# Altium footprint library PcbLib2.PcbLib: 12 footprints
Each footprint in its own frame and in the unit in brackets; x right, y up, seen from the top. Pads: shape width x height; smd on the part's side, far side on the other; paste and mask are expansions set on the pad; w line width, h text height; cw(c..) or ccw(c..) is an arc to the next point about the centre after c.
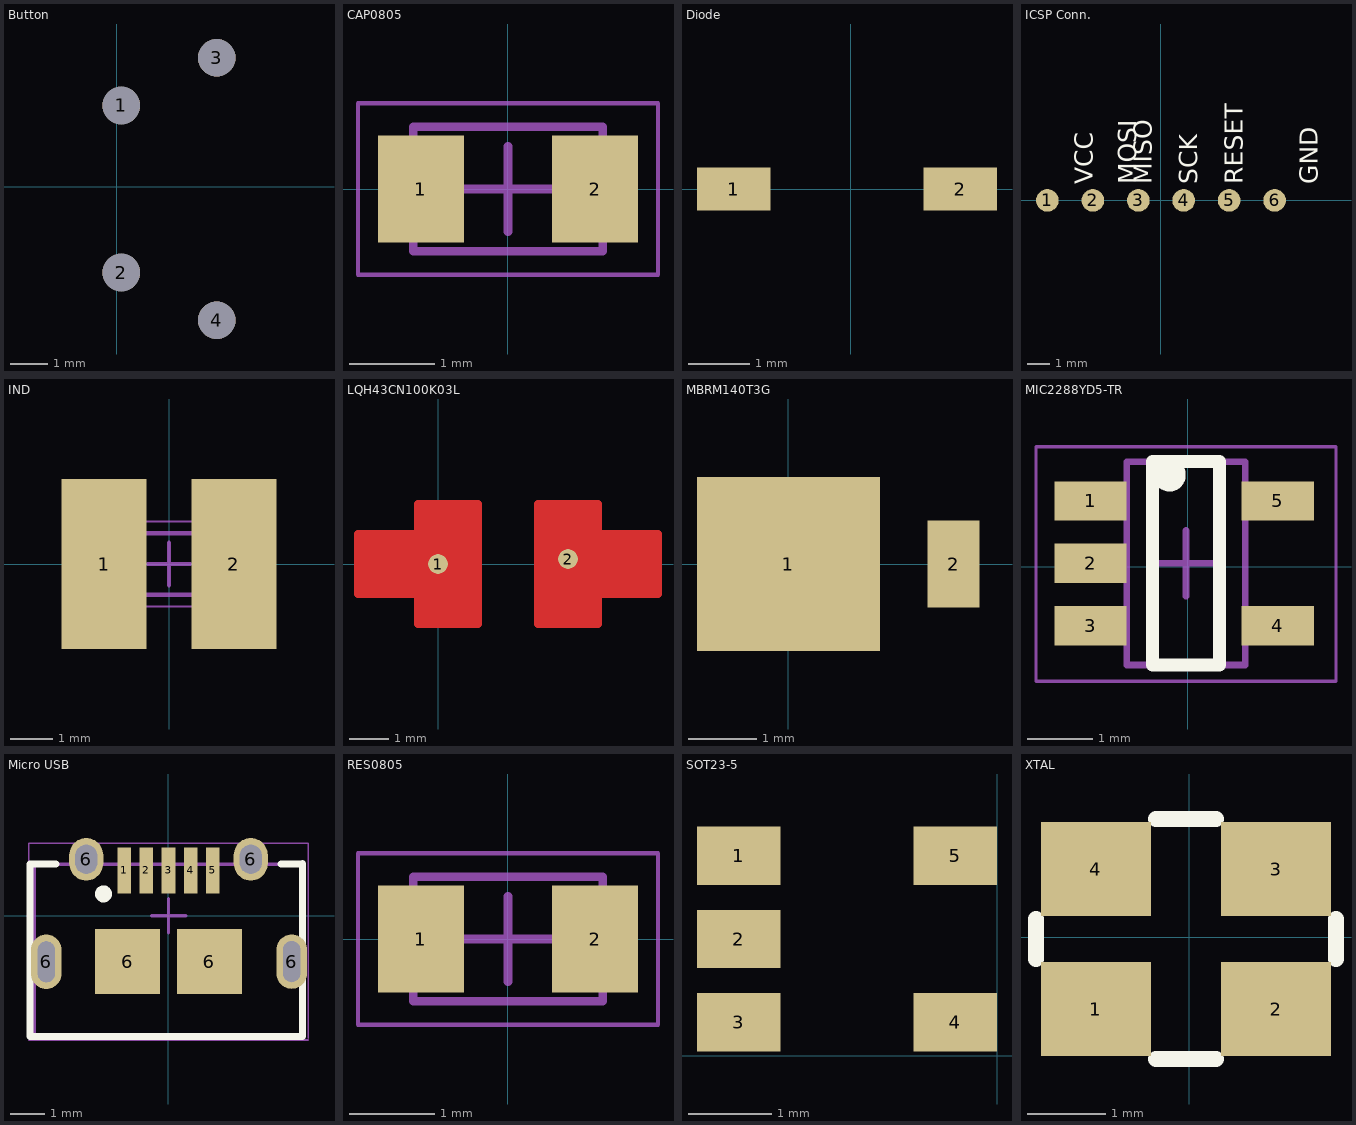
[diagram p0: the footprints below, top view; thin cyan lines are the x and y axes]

## Button [mm]
pads (4):
  round 1 hole 1: 1(0.127,2.159) 2(0.127,-2.286) 3(2.667,3.429) 4(2.667,-3.556)

## CAP0805 [mm]
pads (2):
  rect 1x1.25 smd: 1(-1.016,0) 2(1.016,0)
Mechanical 13:
  lines w0.1: -1.105,-0.725 1.105,-0.725 1.105,0.725 -1.105,0.725 -1.105,-0.725
Mechanical 15:
  lines w0.05: -1.75,-1 1.75,-1 1.75,1 -1.75,1 -1.75,-1
  lines w0.1: -0.5,0 0.5,0 ; 0,-0.5 0,0.5
3D body: height 0.94, standoff 0, extent 0.605,-0.725 1.105,0.725
3D body: height 0.94, standoff 0, extent -1.105,-0.725 -0.605,0.725
3D body: height 0.94, standoff 0, extent -0.605,-0.725 0.605,0.725

## Diode [mm]
pads (2):
  rect 1.2x0.7 smd: 1(-1.905,0) 2(1.778,0)

## ICSP Conn. [mm]
pads (6):
  round 1 smd: 1(-5,0) 2(-3,0) 3(-1,0) 4(1,0) 5(3,0) 6(5,0)
Top Overlay:
  text "VCC" at -3,0.7 h0.8
  text "MOSI" at -1.1,0.7 h0.8
  text "MISO" at -0.4,0.7 h0.8
  text "GND" at 6.9,0.7 h0.8
  text "SCK" at 1.6,0.7 h0.8
  text "RESET" at 3.6,0.7 h0.8

## IND [mm]
pads (2):
  rect 2x4 smd: 1(-1.524,0) 2(1.524,0)
Mechanical 13:
  lines w0.1: -1.105,-0.725 -1.105,0.725 1.105,0.725 1.105,-0.725 -1.105,-0.725
Mechanical 15:
  lines w0.05: -1.75,-1 -1.75,1 1.75,1 1.75,-1 -1.75,-1
  lines w0.1: -0.5,0 0.5,0 ; 0,-0.5 0,0.5
3D body: height 0.94, standoff 0, extent -0.605,-0.725 0.605,0.725
3D body: height 0.94, standoff 0, extent -1.105,-0.725 -0.605,0.725
3D body: height 0.94, standoff 0, extent 0.605,-0.725 1.105,0.725

## LQH43CN100K03L [mm]
pads (2):
  round 0.5 smd: 1(0,0) 2(3.302,0.127)
Top Layer:
  region: 2.54,-1.524 2.54,1.524 4.064,1.524 4.064,0.762 5.588,0.762 5.588,-0.762 4.064,-0.762 4.064,-1.524
  region: -2.032,-0.762 -0.508,-0.762 -0.508,-1.524 1.016,-1.524 1.016,1.524 -0.508,1.524 -0.508,0.762 -2.032,0.762
  lines w0.2: -2.032,-0.762 -2.032,0.762 -0.508,0.762 -0.508,1.524 1.016,1.524 1.016,-1.524 -0.508,-1.524 -0.508,-0.762 -2.032,-0.762 ; 2.54,-1.524 2.54,1.524 4.064,1.524 4.064,0.762 5.588,0.762 5.588,-0.762 4.064,-0.762 4.064,-1.524 2.54,-1.524

## MBRM140T3G [mm]
pads (2):
  rect 2.67x2.54 smd: 1(0,0)
  rect 0.76x1.27 smd: 2(2.413,0)

## MIC2288YD5-TR [mm]
pads (5):
  rect 1.1x0.6 smd: 1(-1.482,1.006) 2(-1.482,0.056) 3(-1.482,-0.894) 4(1.369,-0.894) 5(1.369,1.006)
Top Overlay:
  circle w0.25: c-0.282,1.4 r0.125
  lines w0.2: -0.536,-1.494 -0.536,1.606 0.48,1.606 0.48,-1.494 -0.536,-1.494
Mechanical 13:
  lines w0.1: -0.928,-1.494 0.872,-1.494 0.872,1.606 -0.928,1.606 -0.928,-1.494
Mechanical 15:
  lines w0.05: -2.314,-1.744 2.258,-1.744 2.258,1.834 -2.314,1.834 -2.314,-1.744
  lines w0.1: -0.528,0.056 0.472,0.056 ; -0.028,-0.444 -0.028,0.556
3D body "User Library-SOT23-5-2.step": height 1.45, standoff 0, extent -1.428,-1.373 1.372,1.527
3D body: height 1.45, standoff 0, extent -0.028,0.003 -0.028,0.003

## Micro USB [mm]
pads (11):
  rect 0.4x1.35 smd: 1(-1.292,1.326) 2(-0.642,1.326) 3(0.008,1.326) 4(0.658,1.326) 5(1.308,1.326)
  oval 0.9x1.6 hole 0.5 slot 1.2 at 90 deg: 6(-3.578,-1.355) 6(3.622,-1.349)
  oval 1x1.25 hole 0.85 slot 0.65 at 0 deg: 6(-2.405,1.652) 6(2.421,1.652)
  rect 1.9x1.9 smd: 6(-1.192,-1.349) 6(1.208,-1.349)
Top Overlay:
  circle w0.25: c-1.897,0.636 r0.125
  lines w0.2: -4.056,-2.433 -4.056,-3.549 3.938,-3.549 3.938,-2.536 3.938,1.525 ; -4.056,0.001 -4.056,-0.561 -4.056,-2.402 -4.056,1.518 -3.294,1.518 ; 3.31,1.518 3.931,1.518
Mechanical 13:
  lines w0.1: -3.922,-3.549 3.938,-3.549 3.938,1.501 -3.922,1.501 -3.922,-3.549
Mechanical 15:
  lines w0.05: -4.092,-3.649 4.108,-3.649 ; -4.092,-3.599 -4.092,2.126 4.108,2.126 4.108,-3.599
  lines w0.1: -0.492,0.001 0.508,0.001 ; 0.008,-0.499 0.008,0.501
3D body "10118193-0001lfc.stp": height 2.83, standoff -0.77, extent -3.92,-4.159 3.937,1.501

## RES0805 [mm]
pads (2):
  rect 1x1.25 smd: 1(-1.016,0) 2(1.016,0)
Mechanical 13:
  lines w0.1: -1.105,-0.725 1.105,-0.725 1.105,0.725 -1.105,0.725 -1.105,-0.725
Mechanical 15:
  lines w0.05: -1.75,-1 1.75,-1 1.75,1 -1.75,1 -1.75,-1
  lines w0.1: -0.5,0 0.5,0 ; 0,-0.5 0,0.5
3D body: height 0.94, standoff 0, extent 0.605,-0.725 1.105,0.725
3D body: height 0.94, standoff 0, extent -1.105,-0.725 -0.605,0.725
3D body: height 0.94, standoff 0, extent -0.605,-0.725 0.605,0.725

## SOT23-5 [mm]
pads (5):
  rect 1x0.7 smd: 1(-3.1,2.4) 2(-3.1,1.4) 3(-3.1,0.4) 4(-0.5,0.4) 5(-0.5,2.4)
3D body "User Library-SOT23-5-2.step": height 1.45, standoff 0, extent -3.178,-0.053 -0.378,2.847

## XTAL [mm]
pads (4):
  rect 1.4x1.2 smd: 1(-1.187,-0.911) 2(1.099,-0.911) 3(1.099,0.867) 4(-1.187,0.867)
Top Overlay:
  lines w0.2: -1.949,-0.276 -1.949,0.232 ; -0.425,-1.546 0.337,-1.546 ; -0.425,1.502 0.337,1.502 ; 1.861,-0.276 1.861,0.232
3D body "User Library-Crystal_ECX-32.STEP": height 0.82, standoff 0, extent -1.644,-1.272 1.556,1.228
3D body: height 1.35, standoff 0, extent -0.044,-0.022 -0.044,-0.022
3D body: height 1.35, standoff 0, extent -1.441,0.994 -1.441,0.994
